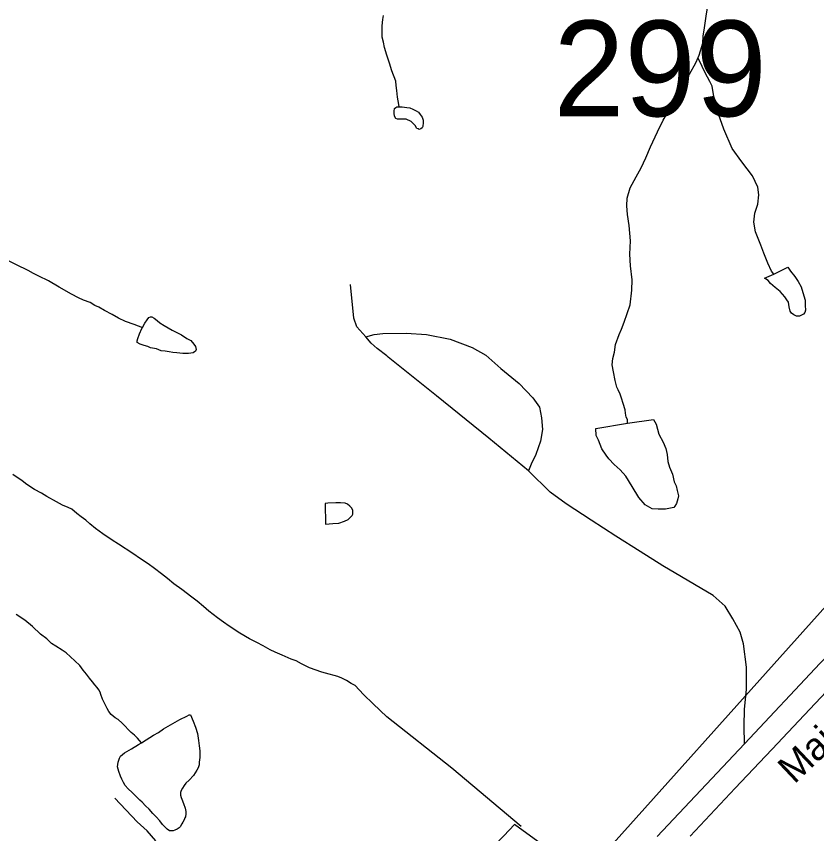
# Model space of a CAD drawing. Extents: x 2001466 to 2224147, y 644118 to 847247.
# Drawn here: x 2073326 to 2076073, y 675951 to 678756 of the extents above; entities that cross this region are included whole.
import ezdxf

# ---------------------------------------------------------------- set-up
doc = ezdxf.new("R2010")
doc.units = 0
for name, color, linetype in [('Exist Boundary Political City Limit New', 7, 'Continuous'), ('Exist Hydrographic Misc Water Feature', 7, 'Continuous'), ('Exist Road Non-System Type 51', 7, 'Continuous'), ('Exist Road Primary US Label', 7, 'Continuous'), ('Exist Road Primary US UnDivided 4 Lane Attributed', 7, 'Continuous'), ('Exist Road Secondary Structure Standard Bridge Number Label', 7, 'Continuous'), ('Map Preparation Boundary City Limit Buffer Line', 7, 'Continuous')]:
    doc.layers.add(name, color=color, linetype=linetype)

msp = doc.modelspace()

# ---------------------------------------------------------------- linework, layer by layer
at = {"layer": 'Exist Boundary Political City Limit New'}
for points in [[(2076834.5, 677545.9), (2075275.9, 675807.4), (2075036.2, 675982.2), (2075000, 675943.8), (2074930.2, 675872.1), (2074830, 675758.7), (2074623, 675542.1), (2074698.1, 675469.7), (2074778.1, 675395.3), (2074832.1, 675348.5), (2074783.6, 675317.2), (2074677.9, 675207.8)], [(2075638.9, 675943), (2075793.5, 676107.4), (2075939.6, 676262.1), (2075955.9, 676279.2), (2076312.4, 676657)]]:
    msp.add_lwpolyline(points, dxfattribs=at)
at = {"layer": 'Exist Hydrographic Misc Water Feature'}
msp.add_line((2074386.6, 677084.5), (2074387.1, 677012.7), dxfattribs=at)
for points in [[(2075666, 678614.1), (2075669.9, 678622), (2075682, 678664), (2075683.8, 678688), (2075687.7, 678715.8), (2075693.4, 678755.9), (2075699.6, 678791.9), (2075707.4, 678841.8), (2075709.4, 678871.9), (2075707.2, 678901.9), (2075699.2, 678966), (2075701, 679020.1), (2075710.7, 679085.9), (2075720.3, 679146.1), (2075734.2, 679204), (2075749.8, 679260), (2075771.8, 679302.2), (2075789.6, 679338), (2075803.8, 679366.3), (2075831.6, 679396.1)], [(2074640.7, 678445), (2074638.6, 678453), (2074634.3, 678478.8), (2074632.5, 678500.9), (2074630.4, 678518.7), (2074628.6, 678532.8), (2074614.5, 678568.6), (2074606.5, 678594.5), (2074598, 678622.6), (2074590.1, 678648.6), (2074586.2, 678666.6), (2074582.1, 678684.7), (2074582.1, 678702.5), (2074582.1, 678722.8), (2074583.9, 678744.8), (2074586, 678758.7)], [(2075423.8, 677359.8), (2075423.8, 677371.9), (2075419.5, 677379.9), (2075417.6, 677394), (2075415.8, 677405.6), (2075409.6, 677427.6), (2075403.7, 677445.5), (2075399.2, 677459.6), (2075391.4, 677473.8), (2075387.5, 677483.7), (2075381.3, 677505.7), (2075375.4, 677535.5), (2075371.3, 677559.5), (2075373.1, 677581.6), (2075378.9, 677603.4), (2075383, 677629.6), (2075394.9, 677663.5), (2075403.1, 677681.7), (2075412.7, 677705.8), (2075422.8, 677735.5), (2075432.8, 677765.6), (2075438.6, 677815.9), (2075440.4, 677851.7), (2075433.8, 677899.7), (2075432, 677939.7), (2075433.8, 677985.7), (2075429.7, 678037.4), (2075423.6, 678075.7), (2075421.5, 678105.6), (2075423.2, 678131.7), (2075433.4, 678167.5), (2075453.3, 678205.4), (2075471.2, 678235.6), (2075487.2, 678269.6), (2075502.7, 678307.8), (2075526.7, 678359.8), (2075546.6, 678399.7), (2075574.7, 678445.8), (2075592.3, 678480), (2075618.2, 678524), (2075636.2, 678557.7), (2075658.4, 678595.8), (2075666, 678614.1)], [(2075926, 677871), (2075918.4, 677881.1), (2075905.9, 677908.9), (2075892.1, 677943), (2075881.9, 677970.9), (2075863.6, 678016.7), (2075857.9, 678048.8), (2075861.4, 678080.7), (2075871.6, 678110.8), (2075875.1, 678142.7), (2075871, 678168.9), (2075853.2, 678208.9), (2075816.9, 678256.6), (2075782.8, 678302.3), (2075754.7, 678368.2), (2075736.7, 678420.5), (2075720.7, 678480.1), (2075714.4, 678516.3), (2075706.4, 678532.1), (2075690.2, 678562.1), (2075680.1, 678583.9), (2075668, 678610.1), (2075666, 678614.1)], [(2074640.7, 678445), (2074650.5, 678445.1), (2074666.7, 678443.1), (2074676.6, 678441.2), (2074686.6, 678437.2), (2074698.7, 678431.3), (2074706.5, 678427.3), (2074712.5, 678419.1), (2074718.8, 678409.2), (2074722.7, 678399.3), (2074723.1, 678391.1), (2074720.9, 678377.3), (2074718.8, 678373.1), (2074714.7, 678369.2), (2074709, 678367.3), (2074704.9, 678369.1), (2074700.6, 678371), (2074694.6, 678381.2), (2074686.6, 678389.3), (2074680.9, 678395.1), (2074676.8, 678396.9), (2074668.6, 678401), (2074664.7, 678402.8), (2074658.7, 678402.9), (2074642.5, 678402.9), (2074635, 678402.9), (2074629, 678405), (2074624.7, 678412.9), (2074622.7, 678423), (2074622.7, 678430.7), (2074624.7, 678438.9), (2074628.4, 678442.8), (2074632.7, 678445), (2074640.7, 678445)], [(2073759.2, 677688.3), (2073755.1, 677688.5), (2073745, 677692.4), (2073731.1, 677698.2), (2073700.9, 677708.1), (2073677, 677720.2), (2073655.2, 677732), (2073629, 677746.1), (2073608.9, 677758.1), (2073595.1, 677763.8), (2073579.4, 677773.9), (2073556.8, 677781.8), (2073539, 677789.8), (2073515.2, 677801.9), (2073472.7, 677825.8), (2073436.8, 677847.8), (2073403, 677863.5), (2073384.8, 677873.6), (2073366.7, 677883.6), (2073326.7, 677903.5), (2073301.1, 677915.5)], [(2075926, 677871), (2075974.2, 677895.3), (2075983.8, 677881.3), (2075998.1, 677863.3), (2076010, 677845.2), (2076020.3, 677827.4), (2076026.2, 677807.5), (2076034.2, 677781.5), (2076034.2, 677763.7), (2076034.6, 677747.4), (2076032.4, 677739.6), (2076028.5, 677733.4), (2076014.8, 677727.3), (2076004.5, 677727.2), (2075994.5, 677731.6), (2075986.7, 677737.3), (2075982.6, 677743.6), (2075978.3, 677759.2), (2075976.4, 677775.3), (2075970.5, 677783.1), (2075964.5, 677793.4), (2075948.3, 677811.2), (2075930.3, 677825.3), (2075914.3, 677839.1), (2075906.3, 677849.2), (2075894.4, 677857.1), (2075926, 677871)], [(2073759.2, 677688.3), (2073767.2, 677702.5), (2073775.2, 677714.3), (2073781.1, 677722.3), (2073786.9, 677724.2), (2073791.2, 677724.4), (2073799, 677720.4), (2073809.2, 677712.3), (2073818.9, 677704.4), (2073833, 677694.5), (2073860.9, 677678.5), (2073893.1, 677662.7), (2073911.1, 677650.6), (2073925.1, 677642.8), (2073934.9, 677630.8), (2073941.3, 677622.5), (2073943.1, 677612.6), (2073941.3, 677606.8), (2073933.5, 677600.6), (2073917.3, 677598.6), (2073897.4, 677598.4), (2073877.3, 677600.6), (2073863.6, 677602.3), (2073851.2, 677604.6), (2073837.5, 677606.7), (2073823.4, 677608.4), (2073807.4, 677614.4), (2073787.1, 677618.3), (2073777.2, 677622.3), (2073765.1, 677626.1), (2073751.4, 677630.2), (2073741.3, 677636.2), (2073740.9, 677642.3), (2073743.2, 677650.1), (2073749.1, 677666.3), (2073757.3, 677684.1), (2073759.2, 677688.3)], [(2075423.8, 677359.8), (2075513.4, 677372.1), (2075521.8, 677356.2), (2075531.9, 677322.3), (2075546, 677294.2), (2075555.8, 677272.4), (2075560.2, 677252.3), (2075562.2, 677228.5), (2075568.2, 677208.5), (2075578.2, 677184.2), (2075584.3, 677158.2), (2075590.7, 677144.3), (2075594.4, 677128.3), (2075598.7, 677110.6), (2075596.4, 677100.4), (2075592.6, 677084.3), (2075586.6, 677074.3), (2075582.5, 677070.4), (2075554.8, 677064.5), (2075528.8, 677064.4), (2075508.7, 677066.2), (2075484.7, 677080), (2075462.3, 677104.1), (2075440.2, 677141.9), (2075418.3, 677178.1), (2075398.4, 677199.7), (2075378.5, 677217.8), (2075360, 677237.6), (2075350.2, 677249.7), (2075336, 677271.7), (2075323.9, 677301.5), (2075315.9, 677317.3), (2075315.7, 677341.3), (2075423.8, 677359.8)], [(2074387.3, 676501.6), (2074375.2, 676505.5), (2074332.9, 676519.6), (2074305, 676533.6), (2074286.8, 676543.6), (2074269.1, 676549.6), (2074239, 676563.4), (2074214.8, 676573.6), (2074197, 676581.5), (2074173, 676595.3), (2074151.2, 676607.2), (2074126.8, 676619.4), (2074093.2, 676639.1), (2074056.7, 676663.3), (2074037, 676677.2), (2074016.9, 676691.2), (2073986.8, 676714.8), (2073968.5, 676730.9), (2073947, 676748.8), (2073929, 676762.9), (2073894.5, 676788.8), (2073866.8, 676808.8), (2073844.7, 676826.8), (2073824.6, 676842.8), (2073800.6, 676860.6), (2073778.7, 676876.6), (2073752.8, 676894.7), (2073726.4, 676912.5), (2073676.5, 676944.3), (2073654.6, 676958.2), (2073622.6, 676980.1), (2073598.2, 676998), (2073578.5, 677014), (2073564.4, 677026.3), (2073548.4, 677038), (2073534.2, 677049.9), (2073516.2, 677064), (2073504.5, 677069.8), (2073484.6, 677078.1), (2073464.5, 677090.1), (2073430.5, 677107.8), (2073412, 677119.9), (2073388, 677131.7), (2073362.2, 677149.7), (2073346.4, 677161.5), (2073314.2, 677183.8)], [(2074387.1, 677012.7), (2074412.9, 677014.9), (2074432.8, 677016.7), (2074453.1, 677023), (2074465, 677028.9), (2074473.2, 677037), (2074478.9, 677043), (2074480.8, 677047.2), (2074481, 677051.2), (2074481, 677061), (2074476.9, 677068.9), (2074470.9, 677075), (2074462.7, 677081.2), (2074454.7, 677084.8), (2074438.5, 677086.8), (2074422.7, 677086.8), (2074394.8, 677085), (2074386.6, 677084.5)], [(2073497.1, 676572), (2073483.2, 676580.2), (2073461.2, 676594.1), (2073447.1, 676604), (2073431.1, 676619.7), (2073409.2, 676636), (2073381.3, 676661.8), (2073355.2, 676684), (2073325.3, 676703.6)], [(2073755.9, 676262.7), (2073742, 676278.6), (2073731.7, 676288.7), (2073719.8, 676298.6), (2073689.3, 676330.4), (2073675.7, 676342.6), (2073665.7, 676348.6), (2073651.5, 676360.5), (2073643.7, 676370.1), (2073637.8, 676380.4), (2073631.6, 676392.2), (2073621.4, 676412.4), (2073615.6, 676428.3), (2073613.6, 676436.4), (2073609.3, 676444.3), (2073603.3, 676452.5), (2073595.3, 676462.3), (2073587.1, 676472.4), (2073577.3, 676484.5), (2073567.3, 676498.1), (2073555.2, 676512.1), (2073543.5, 676528.1), (2073527.3, 676543.9), (2073497.1, 676572)], [(2075058.4, 675975.3), (2074821.1, 676176.3), (2074598, 676352.5), (2074551.3, 676396.8), (2074517.5, 676428.3), (2074489, 676459), (2074475, 676466.8), (2074459.2, 676476.5), (2074443, 676484.3), (2074429.1, 676490), (2074387.3, 676501.6)], [(2073755.9, 676262.7), (2073771.5, 676272.5), (2073797.5, 676288.8), (2073813.7, 676298.5), (2073831.4, 676310.9), (2073863.3, 676328.7), (2073887.3, 676342.9), (2073911.5, 676354.7), (2073919.3, 676358.8), (2073923.6, 676359), (2073933.5, 676336.8), (2073941.3, 676316.9), (2073947.8, 676294.8), (2073951.9, 676271.1), (2073953.6, 676253), (2073955.6, 676234.9), (2073955.6, 676227.1), (2073955.8, 676212.9), (2073953.6, 676197), (2073953.6, 676186.9), (2073949.9, 676176.9), (2073946, 676169), (2073934.1, 676150.9), (2073919.9, 676134.8), (2073908, 676124.8), (2073901.9, 676116.9), (2073896.2, 676106.8), (2073891.8, 676098.9), (2073889.8, 676092.7), (2073890, 676083), (2073892.1, 676075), (2073894.1, 676069), (2073900.3, 676055.1), (2073906, 676038.8), (2073908.3, 676027), (2073908.3, 676018.9), (2073906.2, 676009.1), (2073904.2, 676005), (2073902.3, 675998.8), (2073898, 675990.9), (2073894.1, 675985), (2073888.2, 675975), (2073884.5, 675971.1), (2073878.3, 675966.7), (2073869.9, 675962.7), (2073864.2, 675960.8), (2073858.2, 675960.9), (2073852.3, 675960.9), (2073844.3, 675967), (2073837.9, 675972.8), (2073828.3, 675982.8), (2073818.2, 675994.8), (2073806.1, 676008.9), (2073794.2, 676020.8), (2073782.1, 676034.8), (2073770, 676046.8), (2073758, 676058.8), (2073750, 676066.5), (2073740.1, 676076.5), (2073732.1, 676084.6), (2073724.1, 676092.7), (2073710, 676104.5), (2073700.1, 676116.6), (2073694, 676126.4), (2073688, 676138.3), (2073684.1, 676148.6), (2073677.8, 676164.6), (2073673.7, 676180.6), (2073675.5, 676196.6), (2073680, 676210.5), (2073683.5, 676216.5), (2073697.9, 676228.5), (2073721.9, 676242.7), (2073745.4, 676256.5), (2073755.9, 676262.7)]]:
    msp.add_lwpolyline(points, dxfattribs=at)
at = {"layer": 'Exist Road Non-System Type 51'}
for points in [[(2074597.3, 677590.9), (2074564.1, 677615.8), (2074544.1, 677634.1), (2074525.9, 677655.7), (2074494.3, 677690.6), (2074484.4, 677720.5), (2074472.7, 677835.1)], [(2074525.9, 677655.7), (2074554.1, 677664), (2074584, 677667.3), (2074663.7, 677669), (2074733.5, 677664), (2074814.8, 677647.4), (2074891.2, 677619.1), (2074937.7, 677592.5), (2074989.2, 677547.7), (2075052.3, 677496.2), (2075098.8, 677446.3), (2075122.1, 677414.7), (2075128.7, 677378.2), (2075132, 677338.3), (2075125.4, 677298.4), (2075108.8, 677251.9), (2075093.8, 677218.7), (2075083.9, 677196.4)], [(2075083.9, 677196.4), (2074947.7, 677308.4), (2074768.3, 677453), (2074602.3, 677585.9), (2074597.3, 677590.9)], [(2075825.5, 676259.9), (2075823.9, 676319.7), (2075825.5, 676377.9), (2075832.2, 676446), (2075832.2, 676522.4), (2075822.2, 676602.2), (2075810.6, 676642.1), (2075785.7, 676688.6), (2075759.1, 676731.8), (2075717.6, 676768.4), (2075544.9, 676869.7), (2075467.5, 676918.9), (2075384.4, 676972.1), (2075299.7, 677026.9), (2075213.4, 677083.4), (2075158.6, 677123.3), (2075083.9, 677196.4)], [(2073805, 675926), (2073775.7, 675960.6), (2073740.3, 675991.3), (2073663.9, 676072.9)]]:
    msp.add_lwpolyline(points, dxfattribs=at)
at = {"layer": 'Exist Road Primary US UnDivided 4 Lane Attributed'}
msp.add_lwpolyline([(2075525.8, 675941.5), (2075825.5, 676259.9), (2076085.6, 676536.3), (2076625.6, 677089.2), (2077014.2, 677504.6)], dxfattribs=at)
at = {"layer": 'Map Preparation Boundary City Limit Buffer Line'}
for points in [[(2076834.5, 677545.9), (2075275.9, 675807.4), (2075036.2, 675982.2), (2075000, 675943.8), (2074930.2, 675872.1), (2074830, 675758.7), (2074623, 675542.1), (2074698.1, 675469.7), (2074778.1, 675395.3), (2074832.1, 675348.5), (2074783.6, 675317.2), (2074677.9, 675207.8)], [(2075638.9, 675943), (2075793.5, 676107.4), (2075939.6, 676262.1), (2075955.9, 676279.2), (2076312.4, 676657)]]:
    msp.add_lwpolyline(points, dxfattribs=at)

# ---------------------------------------------------------------- texts
at = {"layer": 'Exist Road Primary US Label'}
msp.add_text('Main', height=95, rotation=43.3512, dxfattribs=at).set_placement((2075996.1, 676119.1))
at = {"layer": 'Exist Road Secondary Structure Standard Bridge Number Label'}
msp.add_text('299', height=328.08, dxfattribs=at).set_placement((2075169.9, 678412.9))

doc.saveas('drawing.dxf')
